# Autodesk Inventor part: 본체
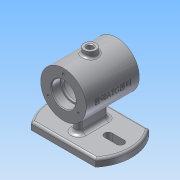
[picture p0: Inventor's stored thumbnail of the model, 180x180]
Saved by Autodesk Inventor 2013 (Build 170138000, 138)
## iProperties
Created: 2017-08
Part Number: 본체
Material: 알루미늄 6061
Document SubType Name: Modeling
Designer: Administrator
Mass: 467.722 g
Surface Area: 486.573 cm^2
Volume: 172.591 cm^3
Density: 2.71 g/cm^3
Author: Administrator
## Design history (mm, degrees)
sketch "스케치1"
  geometry: L1 (-35, 0)-(35, 0); L2 (-35, 16)-(-35, 30); L3 (-35, 30)-(35, 30); L4 (35, 30)-(35, 16); L5 (35, 16)-(23.3, 16); L6 (23, 15.7)-(23, 14); L7 (23, 14)-(20, 14); L8 (20, 14)-(20, 22); L9 (17, 25)-(-17, 25); L10 (-20, 22)-(-20, 14); L11 (-20, 14)-(-23, 14); L12 (-23, 14)-(-23, 15.7); L13 (-23.3, 16)-(-35, 16); A1 r 3 centre (-17, 22) between (-17, 25) and (-20, 22); A2 r 3 centre (17, 22) between (20, 22) and (17, 25); A3 r 0.3 centre (-23.3, 15.7) between (-23, 15.7) and (-23.3, 16); A4 r 0.3 centre (23.3, 15.7) between (23.3, 16) and (23, 15.7); 5 further points
  constraints: 26 end point, 9 parallel, 8 point on circle, 8 tangent, 6 point on line, 4 centre point, 2 collinear, 2 equal radius, 2 horizontal, 2 perpendicular, 2 vertical alignment, 1 coincident, 1 midpoint
  dimensions: "d0" = 70 distance of L1.start L1.end; "d1" = 60 diameter of L3 L1; "d2" = 32 diameter of L13 L1; "d3" = 28 diameter of L11 L1; "d4" = 50 diameter of L9 L1; "d5" = 12 distance of point (-23, 16) L2.start; "d6" = 3 distance of L10.end L11.end; "d7" = 40 distance of point (20, 25) point (-20, 25); "d8" = 3 distance of L6.end L7.end; "d9" = 3 radius of A1; "d10" = 0.3 radius of A3
revolve "회전1" sketch "스케치1" stored, may be unused: angle "d11" = 90 deg
node "작업 평면1"
sketch "스케치2"
  geometry: L1 (-35, 42.426)-(-35, -42.426); L2 (35, 42.426)-(35, -42.426); L3 (15, 5)-(-15, 5); L4 (-15, -5)-(15, -5); A1 r 55 centre (0, 0) between (-35, 42.426) and (-35, -42.426); A2 r 5 centre (-15, 0) between (-15, 5) and (-15, -5); A3 r 5 centre (15, 0) between (15, -5) and (15, 5); 2 further points
  constraints: 8 end point, 8 point on circle, 4 tangent, 3 centre point, 3 parallel, 1 coincident, 1 horizontal alignment, 1 midpoint, 1 perpendicular, 1 vertical, 1 vertical alignment
  dimensions: "d15" = 55 radius of A1; "d16" = 35 distance from line of point (0, 0) L1; "d17" = 5 radius of A3; "d18" = 30 distance of A3.centre A2.centre
extrude "돌출1" join sketch "스케치2" distance "d19" = 10; taper "d20" = 0 deg
extrude "돌출2" join sketch "스케치2" stored distance "d21" = 10; taper "d22" = 0 deg
sketch "스케치3"
  geometry: L1 (35, -42.426)-(35, 42.426) reference; L2 (-35, 42.426)-(-35, -42.426) reference; L3 (-5, -24)-(-5, -40); L4 (5, -40)-(5, -24); A1 r 55 centre (0, 0) between (35, 42.426) and (-35, 42.426) reference; A2 r 5 centre (0, -40) between (-5, -40) and (5, -40); A3 r 5 centre (0, -24) between (5, -24) and (-5, -24)
  constraints: 4 end point, 4 point on circle, 4 tangent, 2 centre point, 2 parallel, 1 vertical alignment
  dimensions: "d24" = 5 radius of A3; "d26" = 16 distance of A2.centre A3.centre; "d27" = 24 distance of A1.centre A3.centre
extrude "돌출3" cut sketch "스케치3" stored distance "d28" = 10; taper "d29" = 0 deg
sketch "스케치4"
  geometry: C1 r 16 at (0, 0) reference; 1 further point
  constraints: 1 vertical alignment
  dimensions: "d30" = 23 distance of C1.centre point (0, 23)
hole "구멍1" sketch "스케치4" at (0, 23) diameter "d31" = 3.242; stored, may be unused: countersink angle "d35" = 90 deg, drill point angle "d37" = 118 deg; dims "d32" = 8, "d33" = 4, "d34" = 2, "d36" = 10
node "작업 평면2"
sketch "스케치5"
  geometry: C1 r 8 at (0, 0); 1 further point
  constraints: 1 centre point, 1 coincident
  dimensions: "d42" = 8 radius of C1
extrude "돌출4" join sketch "스케치5" stored distance "d44" = 10; taper "d45" = 0 deg
hole "구멍2" diameter "d48" = 8; stored, may be unused: countersink angle "d52" = 90 deg, drill point angle "d54" = 118 deg; dims "d46" = 10, "d47" = 10, "d49" = 8, "d50" = 4, "d51" = 2, "d53" = 10
chamfer "모따기1" distance "d55" = 1; stored, may be unused: second distance "d56" = 2, angle "d57" = 45 deg
fillet "모깎기1" dims "d58" = 3, "d59" = 5
node "작업 평면4"
sketch "스케치7"
  geometry: 2 further points
  constraints: 1 coincident, 1 other
feature "엠보싱1" sketch "스케치7" dims "d60" = 0.5, "d61" = 0
node "솔리드1"
mirror "대칭1"
pattern_circular "원형 패턴1" dims angle "d39" = 360 deg
mirror "대칭2"
other parameters: "d14" = -62, "d41" = 37
